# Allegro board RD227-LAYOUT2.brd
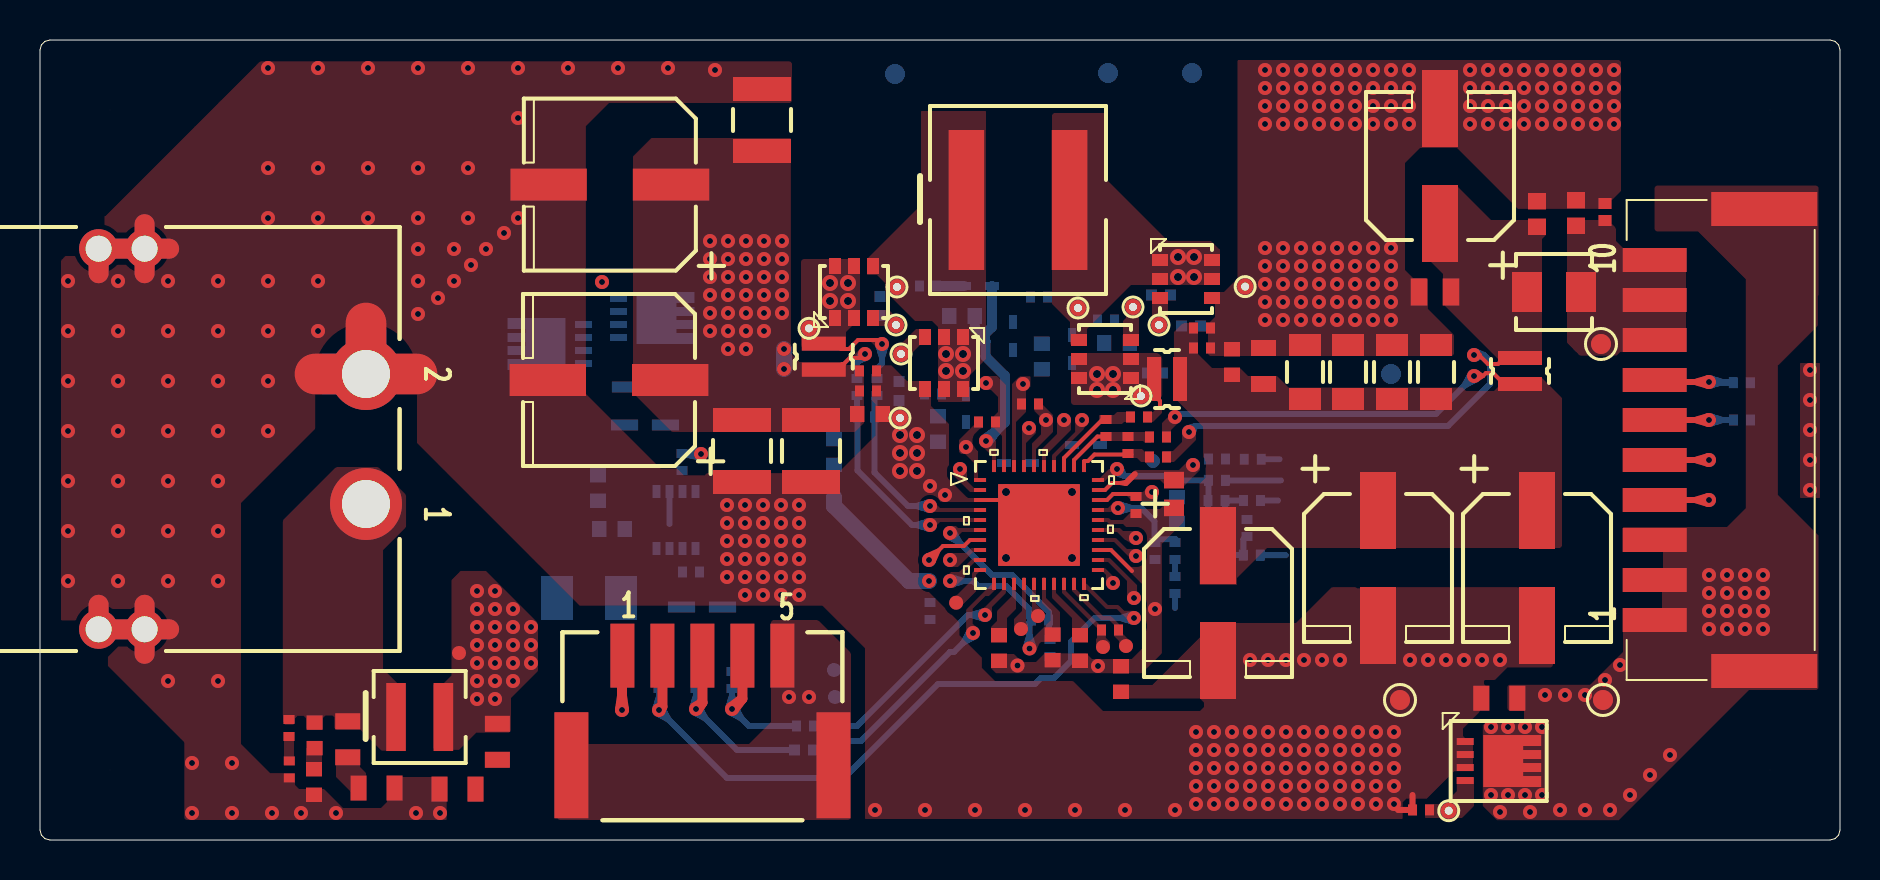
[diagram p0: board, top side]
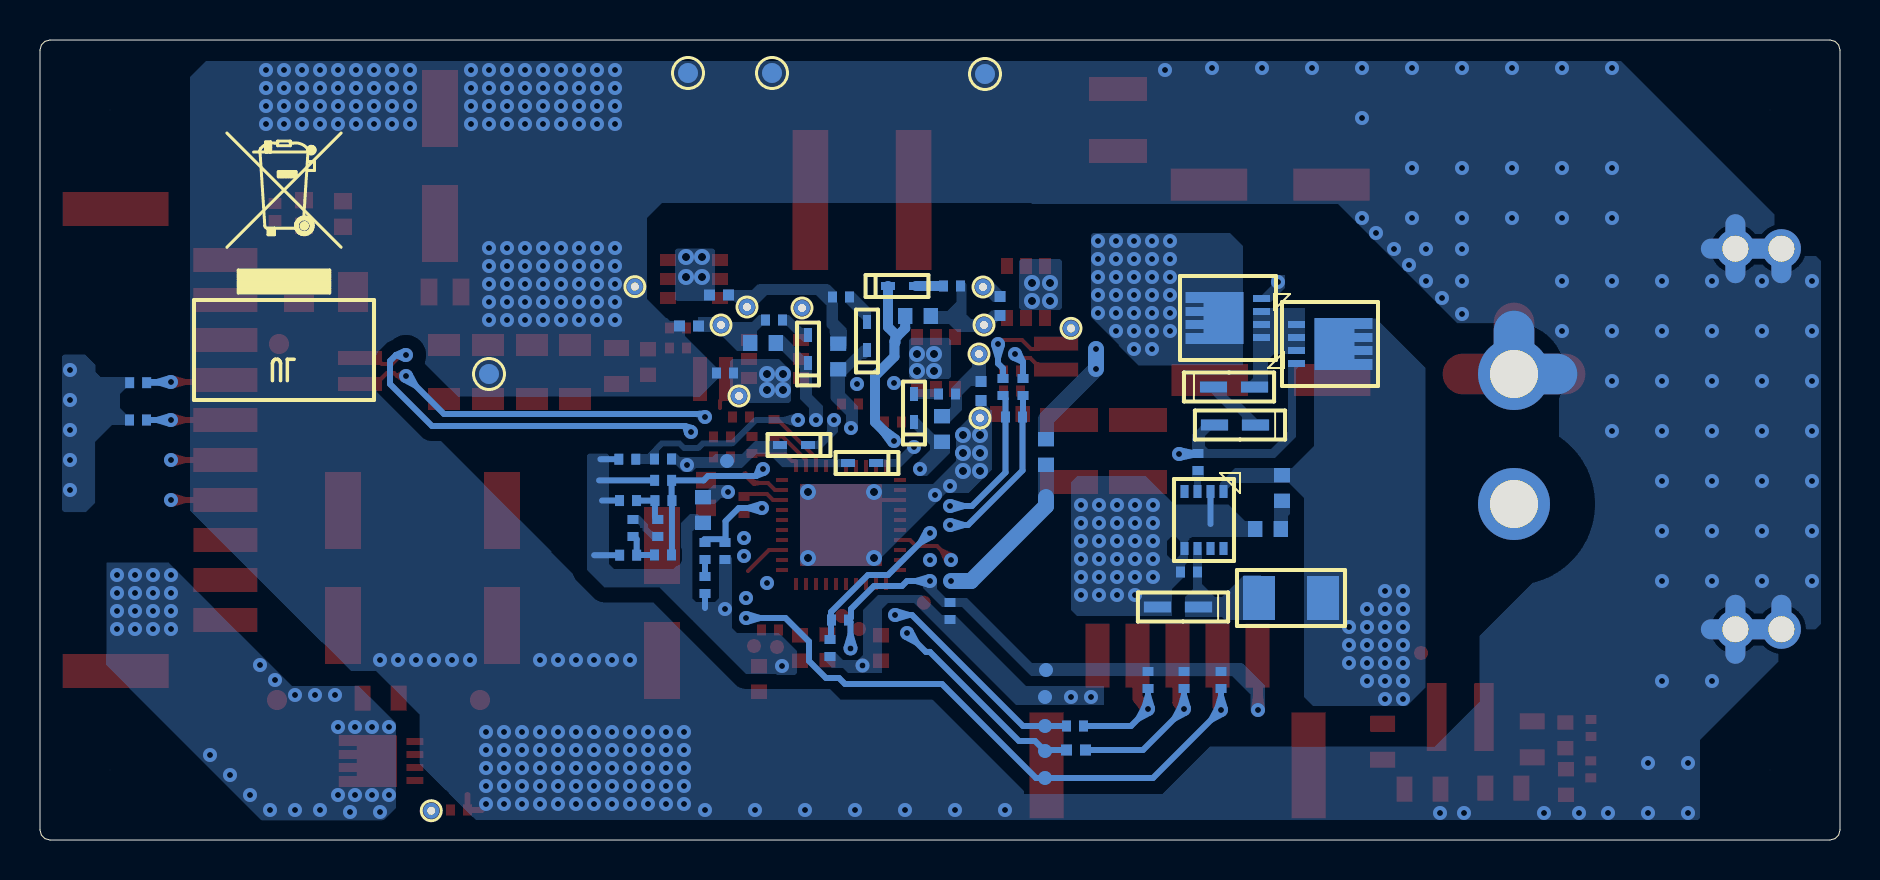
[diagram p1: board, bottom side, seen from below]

Outline 90 x 40 mm; copper layers: TOP, CONDUCTIVE2, CONDUCTIVE3, BOTTOM. Coordinates in mm from the lower left corner of the outline.
Outline path: 0,39.5 0.07,39.75 0.25,39.93 0.5,40 89.5,40 89.75,39.93 89.93,39.75 90,39.5 90,0.5 89.93,0.25 89.75,0.07 89.5,0 0.5,0 0.25,0.07 0.07,0.25 0,0.5 0,39.5

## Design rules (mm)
constraint set DEFAULT: 

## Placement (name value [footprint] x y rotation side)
C201  -  [KC00060AKP]  15.39 5.03 90 top
C202  -  [KC00060AKP]  16.83 2.6 180 top
C203  -  [KCK03340AKP]  36.1 36 270 top
C204  -  [KC00080AKP]  41.5 21.3 180 top
C205  -  [KC01340AKP]  13.73 5.23 90 top
C206  -  [KC01340AKP]  13.7 2.9 90 top
C207  -  [DC837K]  28.49 32.77 0 top
C208  -  [KCK03340AKP]  35.1 19.45 90 top
C209  -  [DC834K]  41.4 22.45 180 top
C210  -  [DC834K]  12.45 5.6 90 top
C211  -  [DC834K]  12.47 3.53 90 top
C212  -  [DC837K]  28.45 23 0 top
C213  -  [KCK03340AKP]  38.55 19.45 90 top
C214  -  [DC834K]  41.4 23.45 180 top
C215  -  [KC00060AKP]  22.87 4.91 90 top
C216  -  [KC00060AKP]  20.87 2.55 0 top
C217  -  [DC834K]  47.35 20.9 0 top
C218  -  [DC834K#2]  32.55 13.4 0 bottom
C219  -  [KC01540AKP01#2]  55.75 23.35 180 bottom
C220  -  [DC834K]  49.5 21.8 180 top
C221  -  [KC00080AKP#2]  27.9 17.6 270 bottom
C222  -  [KC00080AKP#2]  28.6 15.55 0 bottom
C223  -  [DC843R]  58.9 11.85 90 top
C224  -  [KC00140AKP]  69.8 23.4 270 top
C225  -  [KC00060AKP]  61.17 23.7 270 top
C226  -  [DC843R]  74.85 13.6 90 top
C227  -  [KC00140AKP]  67.6 23.4 270 top
C228  -  [KC00080AKP]  59.6 23.9 270 top
C229  -  [DC843R]  66.9 13.6 90 top
C230  -  [KC00140AKP]  65.4 23.4 270 top
C231  -  [DC834K]  58.1 24.6 180 top
C232  -  [KC00140AKP]  63.25 23.4 270 top
C233  -  [KC01540AKP01]  58.1 25.6 180 top
C234  -  [KCK02380AKP01]  74.85 31.3 270 top
C235  -  [DC843R]  70 33.7 270 top
C236  -  [KCK02380AKP01]  76.8 31.35 270 top
C237  -  [KC01540AKP01]  78.25 31.4 270 top
C238  -  [KC00060AKP]  72.97 7.09 0 top
C239  -  [KC00080AKP#2]  56.85 16.5 270 bottom
C240  -  [DC834K]  54.8 16.75 90 top
C241  -  [DC834K#2]  44.5 11.45 270 bottom
C242  -  [KC01670AKP]  50.63 9.63 270 top
C243  -  [KC01560AKP]  56.7 17.3 270 top
C244  -  [DC834K#2]  41.3 21.15 180 bottom
C245  -  [KC00080AKP]  47.95 9.6 270 top
C246  -  [KC00080AKP]  52 9.6 270 top
C247  -  [DC834K]  53.3 20.6 90 top
C248  -  [DC834K]  54.4 19.75 90 top
C249  -  [DC834K#2]  85.1 21 0 bottom
C250  -  [DC834K#2]  85.09 22.86 0 bottom
C251  -  [DC834K#2]  55.75 14.45 270 bottom
C252  -  [DC834K#2]  56.75 12.75 270 bottom
C253  -  [DC834K#2]  58.85 17.98 0 bottom
C254  -  [DC834K#2]  60.6 16.97 0 bottom
C255  -  [DC834K#2]  60.35 15.6 270 bottom
CN201  -  [LOCAL_HVH_280_2P_6_5_1]  16.3 16.8 270 top
CN202  -  [LOCAL_502352_0501]  33.12 5.69 0 top
CN203  -  [LOCAL_502352_1000]  84 20 90 top
D201  -  [D8K022]  33.1 11.65 180 bottom
D202  -  [D8101D1AKP]  48.9 18.85 180 bottom
D203  -  [D8101D1AKP]  46.9 27.7 0 bottom
D204  -  [D8101D1AKP]  46.3 21.6 270 bottom
D205  -  [D8101D1AKP]  48.65 25.2 270 bottom
D206  -  [D8101D1AKP]  51.6 24.55 270 bottom
D207  -  [D8101D1AKP]  52.3 19.75 180 bottom
D208  -  [D8K022]  30.25 20.75 180 bottom
D209  -  [D8K022]  30.3 22.65 0 bottom
FL201  -  [KC00080AKP#2]  39.7 19.4 90 bottom
IC201  -  [SN00281AKP]  31.8 16 0 bottom
IC202  -  [LOCAL_MAX25432BATLGV_1]  49.95 15.75 0 top
L201  -  [LOCAL_XEL_4030_471ME_1]  18.98 6.15 0 top
L202  -  [LOCAL_XAL8080_103MED]  48.9 32 0 top
L203  -  [LOCAL_IHLP1212BZEVR2_1]  75.7 27.4 0 top
NOREF  -  [unnamed]  86.5 3.5 0 top
NOREF#2  -  [unnamed]  3.5 36.5 0 top
NOREF#3  -  [unnamed]  86.5 36.5 0 top
NOREF#4  -  [unnamed]  3.5 3.5 0 top
NOREF#5  -  [#2]  77.8 31.35 180 bottom
NOREF#6  -  [#2]  73.3 22 180 bottom
Q201  -  [SN00612AKP]  25.5 24.8 270 bottom
Q202  -  [SN00612AKP]  30.6 26.1 90 bottom
Q203  -  [LOCAL_TSOP6F]  40.7 27.4 0 top
Q204  -  [LOCAL_TSOP6F]  45.2 23.85 180 top
Q205  -  [LOCAL_TSOP6F]  53.25 24.05 90 top
Q206  -  [LOCAL_TSOP6F]  57.3 28.05 270 top
Q207  -  [SN00612AKP]  72.94 3.95 270 top
R201  -  [KC00080AKP#2]  44.9 20.55 90 bottom
R202  -  [KC00080AKP#2]  46.1 26.2 180 bottom
R203  -  [KC01310AKP#2]  44.4 27.7 180 bottom
R204  -  [LOCAL_KRL2012]  39.19 24.17 90 top
R205  -  [LOCAL_KRL2012]  56.35 23.05 0 top
R206  -  [LOCAL_KRL2012]  74 23.45 90 top
R207  -  [KC01310AKP#2]  44.65 22.3 180 bottom
R208  -  [KC01310AKP#3]  42 26.7 90 bottom
R209  -  [KC01310AKP#3]  42.95 22.45 270 bottom
R210  -  [DR820RF]  27.45 12.1 0 bottom
R211  -  [KC01310AKP#3]  56.05 27.25 0 bottom
R212  -  [KC01310AKP#3]  57.55 25.7 0 bottom
R213  -  [KC01310AKP#2]  49.95 27.15 0 bottom
R214  -  [KC01310AKP#2]  53.3 26 0 bottom
R215  -  [KC00080AKP#2]  50.09 24.18 90 bottom
R216  -  [KC00080AKP#2]  53.85 24.85 0 bottom
R217  -  [DR824K#2]  32.1 18.9 270 bottom
R219  -  [DR810K]  69.75 27.4 0 top
R220  -  [DR824K]  69.05 1.5 0 top
R221  -  [DR824K#2]  34.6 8 90 bottom
R222  -  [DR824K#2]  32.8 8 90 bottom
R223  -  [KC01310AKP#2]  41.85 22.65 270 bottom
R224  -  [KC01310AKP#2]  40.85 22.65 270 bottom
R225  -  [DR824K#2]  30.95 8 90 bottom
R226  -  [DR824K]  53.5 10.5 180 top
R227  -  [KC01310AKP#3]  38.2 4.5 0 bottom
R228  -  [KC01310AKP#2]  38.25 5.7 0 bottom
R229  -  [KC00080AKP]  54.05 8.05 90 top
R230  -  [KC01310AKP]  54.95 21.15 180 top
R231  -  [KC01310AKP]  55.9 20.15 180 top
R232  -  [KC01310AKP]  55.9 19.15 180 top
R233  -  [DR824K#2]  56.75 14.45 270 bottom
R234  -  [KC01310AKP#2]  50 11 180 bottom
R235  -  [DR824K#2]  50.5 9.6 90 bottom
R236  -  [KC00050AKP]  58.83 16.97 0 bottom
R237  -  [KC01310AKP#2]  60.64 19.04 180 bottom
R238  -  [DR824K#2]  59.11 15.6 270 bottom
R239  -  [DR824K#2]  58.85 19.05 180 bottom
R240  -  [DR824K#2]  58.85 14.25 0 bottom
R241  -  [DR824K#2]  60.59 14.24 0 bottom
TP201  -  [TL0_7_A_NOMM]  20.95 9.35 0 top
TP202  -  [TL0_7_A_NOMM]  39.7 17.15 180 bottom
TP203  -  [LOCAL_TL0_4_TH_A]  38.45 25.58 0 top
TP204  -  [LOCAL_TL0_4_TH_A]  42.8 25.75 0 top
TP205  -  [LOCAL_TL0_4_TH_A]  42.85 27.65 0 top
TP206  -  [LOCAL_TL0_4_TH_A]  43.05 24.3 0 top
TP207  -  [LOCAL_TL0_4_TH_A]  43 21.1 0 top
TP208  -  [LOCAL_TL0_4_TH_A]  55.05 22.2 0 top
TP209  -  [LOCAL_TL0_4_TH_A]  54.65 26.65 0 top
TP210  -  [LOCAL_TL0_4_TH_A]  51.9 26.6 0 top
TP211  -  [LOCAL_TL0_4_TH_A]  55.95 25.75 0 top
TP212  -  [LOCAL_TL0_4_TH_A]  60.26 27.67 0 top
TP213  -  [LOCAL_TP_100_A]  78.05 24.8 0 top
TP214  -  [LOCAL_TL0_4_TH_A]  70.44 1.46 0 top
TP215  -  [LOCAL_TP_100_A]  78.15 7 0 top
TP216  -  [LOCAL_TP_100_A]  68 7 0 top
TP217  -  [TL0_7_A_NOMM]  39.7 8.5 180 bottom
TP218  -  [TL0_7_A_NOMM]  39.75 7.15 180 bottom
TP219  -  [TL0_7_A_NOMM]  55.65 18.95 180 bottom
TP220  -  [TL0_7_A_NOMM]  54.3 9.7 0 top
TP221  -  [TL0_7_A_NOMM]  53.15 9.65 0 top
TP222  -  [TL0_7_A_NOMM]  39.75 3.1 180 bottom
TP223  -  [TL0_7_A_NOMM]  39.75 4.45 180 bottom
TP224  -  [TL0_7_A_NOMM]  39.75 5.7 180 bottom
TP225  -  [TL0_7_A_NOMM]  45.81 11.86 0 top
TP226  -  [TL0_7_A_NOMM]  49.05 10.55 0 top
TP227  -  [TL0_7_A_NOMM]  49.9 11.2 0 top
TP231  -  [LOCAL_TP_100_A]  67.55 23.3 180 bottom
TP232  -  [LOCAL_TP_100_A]  57.6 38.35 180 bottom
TP233  -  [LOCAL_TP_100_A]  53.4 38.35 180 bottom
TP234  -  [LOCAL_TP_100_A]  42.75 38.3 180 bottom

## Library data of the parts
C201 C202 C215 C216 = GDM03S00003P: alternate symbols: (T:KC00060AKP;B:KC00060BKP)
C203 C208 C213 = GAS030000261: alternate symbols: (T:KCK03340AKP;B:KCK03340BKP)
C204 C221 C222 C228 C239 C245 C246 = GDM03S000024: alternate symbols: (T:KC00080AKP;B:KC00080BKP)
C205 C206 = GAS030000041: alternate symbols: (T:KC01340AKP;B:KC01340BKP)
C207 C212 = GDM030001780: alternate symbols: (T:DC837K;B:DC937K)
C209 C214 C217 C218 C220 C231 C240 C241 C255 = G924015104Q0: alternate symbols: (T:DC834K;B:DC934K)
C210 C211 = G5103106P106: alternate symbols: (T:DC834K;B:DC934K)
C219 C233 C237 = GAS030000078: alternate symbols: (T:KC01540AKP01,DC834K,KC01540AKP;B:KC01540BKP01,DC834K,KC01540BKP)
C223 C226 C229 C235 = GDM030000304: alternate symbols: (T:DC843R;B:DC943R)
C224 C227 C230 C232 = GDM03S000017: alternate symbols: (T:KC00140AKP;B:KC00140BKP)
C225 C238 = GDM03S000036: alternate symbols: (T:KC00060AKP;B:KC00060BKP)
C234 C236 = GAS030000086: alternate symbols: (T:KCK02380AKP01;B:KCK02380BKP01)
C242 = GDM030002537: alternate symbols: (T:KC01670AKP;B:KC01670BKP)
C243 = GDM030002140: alternate symbols: (T:KC01560AKP;B:KC01560BKP)
C244 C247 C248 C251 = G5103105X103: alternate symbols: (T:DC834K;B:DC934K)
C249 C250 = G5103106G107: alternate symbols: (T:DC834K;B:DC934K)
C252 = G36030133517: alternate symbols: (T:DC834K;B:DC934K)
C253 = G510310FQ104: alternate symbols: (T:DC834K;B:DC934K)
C254 = G510310E1104: alternate symbols: (T:DC834K;B:DC934K)
CN201 = HVH-280-2P-6_5DS: alternate symbols: (T:Local_HVH_280_2P_6_5_1;B:Local_HVH_280_2P_6_5_1_B)
CN202 = 502352-0501: alternate symbols: (T:Local_502352_0501;B:Local_502352_0501_B)
CN203 = 502352-1000: alternate symbols: (T:Local_502352_1000;B:Local_502352_1000_B)
D201 D208 D209 = K4200015: alternate symbols: (T:D8K022;B:D9K022)
D202-D207 = GDM42S000008: alternate symbols: (T:D8101D1AKP;B:D8101D1BKP)
FL201 = GDM130000101: alternate symbols: (T:KC00080AKP;B:KC00080BKP)
IC201 = GDM410000462: alternate symbols: (T:SN00281AKP;B:SN00281BKP)
IC202 = MAX25432BATLGV+
L201 = XEL-4030-471MEC: alternate symbols: (T:Local_XEL_4030_471ME_1;B:Local_XEL_4030_471ME_1_B)
L202 = XAL8080-103MED: alternate symbols: (T:Local_XAL8080_103MED;B:Local_XAL8080_103MED_B)
L203 = IHLP1212BZEVR22M5A: alternate symbols: (T:Local_IHLP1212BZEVR2_1;B:Local_IHLP1212BZEVR2_1_B)
Q201 Q202 Q207 = K4100929: alternate symbols: (T:SN00612AKP;B:SN00612BKP)
Q203-Q206 = GDM410000109
R201 R202 R215 R216 R229 = G8800256207A: alternate symbols: (T:KC00080AKP;B:KC00080BKP)
R203 R207-R209 R211-R214 R223 R224 R227 R228 R230-R232 R234 R237 = GAS010000128: alternate symbols: (T:KC01310AKP,DC934K,DR924K,DR824K;B:KC01310BKP,DC934K,DR924K,DR824K)
R204 R205 = KRL2012E-M-R003-F
R206 = KRL2012E-M-R005-F: alternate symbols: (T:Local_KRL2012;B:Local_KRL2012_B)
R210 = G510110RM109: alternate symbols: (T:DR820RF;B:DR901RF)
R217 = G510110CB102: alternate symbols: (T:DR824K;B:DR924K)
R219 = G510110AC101: alternate symbols: (T:DR810K;B:DR910K)
R220 R225 = G510110EF108: alternate symbols: (T:DR824K;B:DR924K)
R221 R222 = G510110E7102: alternate symbols: (T:DR824K;B:DR924K)
R226 R233 R235 R238-R241 = G510110M9109: alternate symbols: (T:DR824K;B:DR924K)
R236 = GDM010002829: alternate symbols: (T:KC00050AKP;B:KC00050BKP)
TP201 TP202 TP217-TP227 = TL0.7_noMM: alternate symbols: (T:TL0_7_A_noMM;B:TL0_7_B_noMM)
TP203-TP212 TP214 = TL0.4_TH: alternate symbols: (T:Local_TL0_4_TH_A;B:Local_TL0_4_TH_B)
TP213 TP215 TP216 TP231-TP234 = TP-100: alternate symbols: (T:Local_TP_100_A;B:Local_TP_100_B)

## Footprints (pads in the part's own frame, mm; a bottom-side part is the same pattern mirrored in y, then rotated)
D8K022
  rect 1.36x0.55 smd: A(-1.025,0) C(1.025,0)
D8101D1AKP
  rect 0.7x0.4 smd: A(-0.7,0) C(0.7,0)
DC834K
  rect 0.45x0.55 smd: 1(-0.425,0) 2(0.425,0)
DC834K#2
  rect 0.45x0.55 smd: 1(0.425,0) 2(-0.425,0)
DC837K
  rect 3.82x1.6 smd: 1(-3.06,0) 2(3.06,0)
DC843R
  rect 3.85x1.8 smd: 1(-2.875,0) 2(2.875,0)
DR810K
  rect 0.83x1.35 smd: 1(-0.8,0) 2(0.8,0)
DR820RF
  rect 1.6x2.2 smd: 1(1.6,0) 2(-1.6,0)
DR824K
  rect 0.45x0.55 smd: 1(-0.425,0) 2(0.425,0)
DR824K#2
  rect 0.45x0.55 smd: 1(0.425,0) 2(-0.425,0)
KC00050AKP
  rect 0.45x0.55 smd: 1(0.425,0) 2(-0.425,0)
KC00060AKP
  rect 0.8x1.25 smd: 1(-0.9,0) 2(0.9,0)
KC00080AKP
  rect 0.72x0.8 smd: 1(-0.64,0) 2(0.64,0)
KC00080AKP#2
  rect 0.72x0.8 smd: 1(0.64,0) 2(-0.64,0)
KC00140AKP
  rect 1.1x1.6 smd: 1(-1.35,0) 2(1.35,0)
KC01310AKP
  rect 0.45x0.55 smd: 1(-0.425,0) 2(0.425,0)
KC01310AKP#2
  rect 0.45x0.55 smd: 1(0.425,0) 2(-0.425,0)
KC01310AKP#3
  rect 0.55x0.55 smd: 1(0.475,0) 2(-0.475,0)
KC01340AKP
  rect 0.72x0.8 smd: 1(-0.64,0) 2(0.64,0)
KC01540AKP01
  rect 0.45x0.55 smd: 1(-0.425,0) 2(0.425,0)
KC01540AKP01#2
  rect 0.45x0.55 smd: 1(0.425,0) 2(-0.425,0)
KC01560AKP
  rect 0.83x1 smd: 1(-0.695,0) 2(0.695,0)
KC01670AKP
  rect 0.72x0.8 smd: 1(-0.64,0) 2(0.64,0)
KCK02380AKP01
  rect 0.82x0.9 smd: 1(-0.64,0) 2(0.64,0)
KCK03340AKP
  rect 1.2x2.9 smd: 1(-1.55,0) 2(1.55,0)
LOCAL_502352_0501
  rect 1.2x3.2 smd: 1(-4,3.53) 2(-2,3.53) 3(0,3.53) 4(2,3.53) 5(4,3.53)
  rect 1.7x5.3 smd: 1T(-6.55,-1.95) 2T(6.55,-1.95)
LOCAL_502352_1000
  rect 1.2x3.2 smd: 1(-9,3.265) 2(-7,3.265) 3(-5,3.265) 4(-3,3.265) 5(-1,3.265) 6(1,3.265) 7(3,3.265) 8(5,3.265) 9(7,3.265) 10(9,3.265)
  rect 1.7x5.3 smd: 1T(-11.55,-2.215) 2T(11.55,-2.215)
LOCAL_HVH_280_2P_6_5_1
  round 3.6 hole 2.4: 1(0,0) 2(-6.5,0)
  round 1.95 hole 1.3: 1T(6.265,-13.37) 2T(6.265,-11.07) 3T(-12.765,-11.07) 4T(-12.765,-13.37)
LOCAL_IHLP1212BZEVR2_1
  custom 0.375x0.375 smd: 1(-1.35,0) 2(1.35,0)
LOCAL_KRL2012
  custom 0.175x0.175 smd: 1(-0.65,0) 2(0.65,0)
LOCAL_MAX25432BATLGV_1
  custom 0.05x0.05 smd: 1(-2.948,2.25) 2(-2.948,1.75) 3(-2.948,1.25) 4(-2.948,0.75) 5(-2.948,0.25) 6(-2.948,-0.25) 7(-2.948,-0.75) 8(-2.948,-1.25) 9(-2.948,-1.75) 10(-2.948,-2.25) 11(-2.25,-2.948) 12(-1.75,-2.948) 13(-1.25,-2.948) 14(-0.75,-2.948) 15(-0.25,-2.948) 16(0.25,-2.948) 17(0.75,-2.948) 18(1.25,-2.948) 19(1.75,-2.948) 20(2.25,-2.948) 21(2.948,-2.25) 22(2.948,-1.75) 23(2.948,-1.25) 24(2.948,-0.75) 25(2.948,-0.25) 26(2.948,0.25) 27(2.948,0.75) 28(2.948,1.25) 29(2.948,1.75) 30(2.948,2.25) 31(2.25,2.948) 32(1.75,2.948) 33(1.25,2.948) 34(0.75,2.948) 35(0.25,2.948) 36(-0.25,2.948) 37(-0.75,2.948) 38(-1.25,2.948) 39(-1.75,2.948) 40(-2.25,2.948)
  custom 1.022x1.022 smd: 41(0,0)
LOCAL_TL0_4_TH_A
  round 0.8 hole 0.4: 1(0,0)
LOCAL_TP_100_A
  custom 0.25x0.25 smd: 1(0,0)
LOCAL_TSOP6F
  rect 0.6x0.8 smd: 1(-0.95,-1.3) 2(0,-1.3) 3(0.95,-1.3) 4(0.95,1.3) 5(0,1.3) 6(-0.95,1.3)
LOCAL_XAL8080_103MED
  custom 0.445x0.445 smd: 1(-2.58,0) 2(2.58,0)
LOCAL_XEL_4030_471ME_1
  custom 0.245x0.245 smd: 1(-1.185,0) 2(1.185,0)
SN00281AKP
  rect 0.4x0.65 smd: 1(-0.975,-1.425) 2(-0.325,-1.425) 3(0.325,-1.425) 4(0.975,-1.425) 5(0.975,1.425) 6(0.325,1.425) 7(-0.325,1.425) 8(-0.975,1.425)
SN00612AKP
  rect 0.35x0.85 smd: 1(-0.975,-1.675) 2(-0.325,-1.675) 3(0.325,-1.675) 4(0.975,-1.675)
  custom 0.65x0.65 smd: 5(0,0.675)
TL0_7_A_NOMM
  round 0.7 smd: 1(0,0)
unnamed
  round 0.01 hole 3 unplated: (0,0)

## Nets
GND_A: C239.1 C240.1 C241.1 C242.2 C243.2 C245.2 C246.2 C249.1 C250.1 C251.1 C252.1 C253.1 C254.1 CN202.1T CN202.2T CN202.5 IC202.23 IC202.26 R229.2 R235.2 R237.2 R241.1 TP218.1
GND_P: C202.1 C203.1 C204.1 C206.1 C207.1 C208.1 C209.1 C211.1 C212.1 C213.1 C214.1 C216.1 C218.1 C219.2 C222.1 C223.1 C224.1 C225.1 C226.1 C227.1 C228.1 C229.1 C230.1 C231.1 C232.1 C233.1 C234.1 C235.1 C236.1 C237.1 C238.1 CN201.1T CN201.2 CN201.2T CN201.3T CN201.4T D201.A IC201.2 IC201.5 IC202.3 IC202.41 Q204.4 Q206.4 Q207.1 Q207.2 Q207.3 R209.1 R212.1 R219.1 R220.1 R229.1 TP207.1 TP212.1 TP216.1 TP231.1 TP232.1 TP233.1 TP234.1
VBAT: C239.2 C240.2 FL201.2 IC202.28 TP202.1
VBUS: C236.2 C237.2 CN203.8 CN203.9 CN203.10 L203.2 TP213.1
VDD: C241.2 C242.1 CN202.1 IC202.9 IC202.16 R221.1 R222.1 R225.1 R234.1 TP217.1
VIN: C201.2 C205.2 C210.2 CN201.1 L201.1
VIN2: C215.2 C221.2 IC201.1 L201.2 Q201.5 R210.2 TP201.1
ADDR: IC202.34 R237.1 R239.2
ALERT: CN202.2 IC202.20 R225.2 TP222.1
BIAS: C243.1 D202.A D207.A IC202.29 R239.1 TP219.1
BST1: C217.1 D202.C IC202.1
BST2: C220.1 D207.C IC202.36
CSN1: Q203.1 Q203.2 Q203.5 Q203.6 R204.2 R223.2 TP203.1
CSN2: C234.2 C235.2 L203.1 R206.2 R219.2 R232.1
CSP1: C203.2 C204.2 C207.2 C208.2 C209.2 C212.2 C213.2 C214.2 FL201.1 Q202.5 R204.1 R224.2
CSP2: C219.1 Q205.1 Q205.2 Q205.5 Q205.6 R205.1 R230.1 TP208.1
DH1: D203.C IC202.40 R202.2
DH1_Q: Q203.3 R202.1 R203.1 R208.2 TP204.1
DH2: D205.C IC202.37 R215.2
DH2_Q: Q205.3 R211.2 R213.1 R215.1 TP209.1
DL1: D204.C IC202.2 R201.2
DL1_Q: Q204.3 R201.1 R207.1 R209.2 TP206.1
DL2: D206.C IC202.35 R216.2
DL2_Q: Q206.3 R212.2 R214.1 R216.1 TP211.1
GDRV: IC202.8 Q207.4 R220.2 TP214.1
HVCC1: C250.2 CN203.7 IC202.25
HVCC2: C249.2 CN203.6 IC202.24
HVDM: CN203.5 IC202.21
HVDP: CN203.4 IC202.22
HVEN: IC202.6 R234.2 R235.1
LX1: C217.2 IC202.39 L202.1 Q203.4 Q204.1 Q204.2 Q204.5 Q204.6 R208.1 TP205.1
LX2: C220.2 IC202.38 L202.2 Q205.4 Q206.1 Q206.2 Q206.5 Q206.6 R211.1 TP210.1
OUT: C223.2 C224.2 C225.2 C226.2 C227.2 C228.2 C229.2 C230.2 C231.2 C232.2 C233.2 R205.2 R206.1 R231.1
SCL: CN202.3 R222.2 R227.2
SDA: CN202.4 R221.2 R228.2
SHLD_SNS: C238.2 CN203.1 CN203.1T CN203.2 CN203.2T CN203.3 IC202.7 Q207.5 TP215.1
SIG247: C218.2 D201.C IC201.6 R210.1
SIG310: C251.2 IC202.27 R233.2
SIG311: C252.2 R233.1
SIG313: C254.2 R236.1 R238.2
SIG316: C255.1 R240.1 R241.2
SIG317: C255.2 R238.1
SIG318: C253.2 IC202.30 R236.2 R240.2
SIG319: C247.1 C248.2 IC202.32 R231.2
SIG324: C248.1 IC202.31 R232.2
SIG328: C247.2 IC202.33 R230.2
SIG335: C244.1 IC202.5 R224.1
SIG337: C244.2 IC202.4 R223.1
SIG341: IC202.10 TP225.1
SIG344: IC202.19 R226.1 TP220.1
SIG345: IC202.18 R226.2 TP221.1
SIG346: C245.1 IC202.13
SIG347: C246.1 IC202.17
SIG349: IC202.14 TP226.1
SIG350: IC202.15 TP227.1
SIG369: IC202.11 R227.1 TP223.1
SIG370: IC202.12 R228.1 TP224.1
SIG395: C201.1 C202.2
SIG396: C205.1 C206.2
SIG397: C210.1 C211.2
SIG411: C215.1 C216.2
SIG422: D203.A R203.2
SIG423: D204.A R207.2
SIG424: C221.1 C222.2
SIG425: D205.A R213.2
SIG426: D206.A R214.2
SIG433: IC201.3 R217.1
SIG436: D209.A Q201.1 Q201.2 Q201.3 Q202.1 Q202.2 Q202.3
SIG437: D208.C D209.C
SIG438: D208.A Q201.4 Q202.4 R217.2

Pads without a net: IC201 4 7 8

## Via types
v1: diameter 0.7, hole 0.3, TOP to BOTTOM, 444 vias
v2: diameter 0.8, hole 0.4, TOP to BOTTOM, 26 vias

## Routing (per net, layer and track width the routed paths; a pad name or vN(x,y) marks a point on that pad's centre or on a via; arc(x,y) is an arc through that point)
GND_A: length 8.7
  TOP w0.2: 54.6,13.45 53.55,14.5 IC202.23
  BOTTOM w0.3: C253.1 62.05,17.98 ; R241.1 62.29,14.24 ; 61.11,19.04 61.98,19.04 ; C254.1 61.9,16.97 ; C252.1 56.75,11.6
  vias: v1(37.45,7.15) v1(38.45,7.15) v1(48.88,8.72) v1(52.9,8.7) v1(55.75,11.55) v1(88.5,23.5) v1(88.5,22) v1(88.5,20.5) v1(88.5,19) v1(88.5,17.5)
GND_P: length 95.4
  TOP w0.2: IC202.3 48.3,17
  TOP w0.3: 68.63,2.25 R220.1 67.9,1.5
  TOP w1: CN201.2T 6.46,10.54 ; CN201.2T 5.23,11.76 ; CN201.2T CN201.1T 2.93,11.76 ; CN201.2T 5.23,9.31 ; CN201.3T 5.23,28.34 ; CN201.3T 6.46,29.57 ; CN201.3T 5.23,30.79 ; CN201.3T CN201.4T 2.93,28.34
  TOP w2.032: CN201.2 18.85,23.3 ; CN201.2 16.3,25.85 ; CN201.2 13.75,23.3
  CONDUCTIVE2 w1: CN201.3T 5.23,28.09 ; CN201.3T 5.23,31.04 ; CN201.3T CN201.4T 2.93,28.06 ; CN201.3T 6.71,29.57 ; CN201.2T 6.71,10.54 ; CN201.2T CN201.1T 2.93,12.01 ; CN201.2T 5.23,12.01 ; CN201.2T 5.23,9.06
  CONDUCTIVE2 w2.032: CN201.2 16.3,25.6 ; CN201.2 14,23.3 ; CN201.2 16.3,21.6 ; CN201.2 18.6,23.3
  CONDUCTIVE3 w1: CN201.2T 6.71,10.54 ; CN201.2T CN201.1T 2.93,12.01 ; CN201.2T 5.23,9.06 ; CN201.2T 5.23,12.01 ; CN201.3T 6.71,29.57 ; CN201.3T CN201.4T 2.93,27.97 ; CN201.3T 5.23,27.97 ; CN201.3T 5.23,31.04
  CONDUCTIVE3 w2.032: 16.3,25.6 CN201.2 ; CN201.2 14,23.3 ; CN201.2 16.3,21.65 ; CN201.2 18.6,23.3
  BOTTOM w0.3: IC201.2 31.48,15.8
  BOTTOM w1: CN201.2T 5.23,11.76 ; CN201.2T 5.23,9.31 ; CN201.2T CN201.1T 2.93,11.76 ; CN201.2T 6.46,10.54 ; 2.93,28.34 CN201.4T CN201.3T ; CN201.3T 5.23,30.79 ; CN201.3T 5.23,28.34 ; CN201.3T 6.46,29.57
  BOTTOM w2.032: 16.3,25.45 CN201.2 14.15,23.3
  vias: v1(1.4,27.95) v1(1.4,25.45) v1(1.4,22.95) v1(1.4,20.45) v1(1.4,17.95) v1(1.4,15.45) v1(1.4,12.95) v1(3.9,27.95) v1(3.9,25.45) v1(3.9,22.95) v1(3.9,20.45) v1(3.9,17.95) v1(3.9,15.45) v1(3.9,12.95) v1(6.4,27.95) v1(6.4,25.45) v1(6.4,22.95) v1(6.4,20.45) v1(6.4,17.95) v1(6.4,15.45) v1(6.4,12.95) v1(6.4,7.95) v1(7.6,3.85) v1(7.6,1.35) v1(8.9,27.95) v1(8.9,25.45) v1(8.9,22.95) v1(8.9,20.45) v1(8.9,17.95) v1(8.9,15.45) v1(8.9,12.95) v1(8.9,7.95) v1(9.6,3.85) v1(9.6,1.35) v1(11.4,38.6) v1(11.4,33.6) v1(11.4,31.1) v1(11.4,27.95) v1(11.4,25.45) v1(11.4,22.95) v1(11.4,20.45) v1(11.6,1.35) v1(13.05,1.35) v1(13.9,38.6) v1(13.9,33.6) v1(13.9,31.1) v1(13.9,27.95) v1(13.9,25.45) v1(14.8,1.35) v1(16.4,38.6) v1(16.4,33.6) v1(16.4,31.1) v1(18.8,1.35) v1(18.9,38.6) v1(18.9,33.6) v1(18.9,31.1) v1(18.9,29.55) v1(18.9,27.95) v1(18.9,26.3) v1(19.9,27.1) v1(20,1.35) v1(20.7,29.55) v1(20.7,27.95) v1(21.4,38.6) v1(21.4,33.6) v1(21.4,31.1) v1(21.55,28.75) v1(22.3,29.55) v1(23.2,30.35) v1(23.9,38.6) v1(23.9,36.1) v1(23.9,31.1) v1(26.4,38.6) v1(28.9,38.6) v1(31.4,38.6) v1(33.75,38.5) v1(34.35,16.75) v1(34.35,15.85) v1(34.35,14.95) v1(34.35,14.05) v1(34.35,13.15) v1(35.25,16.75) v1(35.25,15.85) v1(35.25,14.95) v1(35.25,14.05) v1(35.25,13.15) v1(35.25,12.25) v1(36.15,16.75) v1(36.15,15.85) v1(36.15,14.95) v1(36.15,14.05) v1(36.15,13.15) v1(36.15,12.25) v1(37.05,16.75) v1(37.05,15.85) v1(37.05,14.95) v1(37.05,14.05) v1(37.05,13.15) v1(37.05,12.25) v1(37.95,16.75) v1(37.95,15.85) v1(37.95,14.95) v1(37.95,14.05) v1(37.95,13.15) v1(37.95,12.25) v1(41.75,1.5) v1(44.25,1.5) v1(44.5,17.7) v1(45.25,17.25) v1(46.75,1.5) v1(49.25,1.5) v1(51.75,1.5) v1(54.25,1.5) v1(56.75,1.5) v1(57.8,5.4) v1(57.8,4.5) v1(57.8,3.6) v1(57.8,2.7) v1(57.8,1.8) v1(58.7,5.4) v1(58.7,4.5) v1(58.7,3.6) v1(58.7,2.7) v1(58.7,1.8) v1(59.6,5.4) v1(59.6,4.5) v1(59.6,3.6) v1(59.6,2.7) v1(59.6,1.8) v1(60.5,9) v1(60.5,5.4) v1(60.5,4.5) v1(60.5,3.6) v1(60.5,2.7) v1(60.5,1.8) v1(61.25,38.5) v1(61.25,37.6) v1(61.25,36.7) v1(61.25,35.8) v1(61.25,29.6) v1(61.25,28.7) v1(61.25,27.8) v1(61.25,26.9) v1(61.25,26) v1(61.4,9) v1(61.4,5.4) v1(61.4,4.5) v1(61.4,3.6) v1(61.4,2.7) v1(61.4,1.8) v1(62.15,38.5) v1(62.15,37.6) v1(62.15,36.7) v1(62.15,35.8) v1(62.15,29.6) v1(62.15,28.7) v1(62.15,27.8) v1(62.15,26.9) v1(62.15,26) v1(62.3,9) v1(62.3,5.4) v1(62.3,4.5) v1(62.3,3.6) v1(62.3,2.7) v1(62.3,1.8) v1(63.05,38.5) v1(63.05,37.6) v1(63.05,36.7) v1(63.05,35.8) v1(63.05,29.6) v1(63.05,28.7) v1(63.05,27.8) v1(63.05,26.9) v1(63.05,26) v1(63.2,9) v1(63.2,5.4) v1(63.2,4.5) v1(63.2,3.6) v1(63.2,2.7) v1(63.2,1.8) v1(63.95,38.5) v1(63.95,37.6) v1(63.95,36.7) v1(63.95,35.8) v1(63.95,29.6) v1(63.95,28.7) v1(63.95,27.8) v1(63.95,26.9) v1(63.95,26) v1(64.1,9) v1(64.1,5.4) v1(64.1,4.5) v1(64.1,3.6) v1(64.1,2.7) v1(64.1,1.8) v1(64.85,38.5) v1(64.85,37.6) v1(64.85,36.7) v1(64.85,35.8) v1(64.85,29.6) v1(64.85,28.7) v1(64.85,27.8) v1(64.85,26.9) v1(64.85,26) v1(65,9) v1(65,5.4) v1(65,4.5) v1(65,3.6) v1(65,2.7) v1(65,1.8) v1(65.75,38.5) v1(65.75,37.6) v1(65.75,36.7) v1(65.75,35.8) v1(65.75,29.6) v1(65.75,28.7) v1(65.75,27.8) v1(65.75,26.9) v1(65.75,26) v1(65.9,5.4) v1(65.9,4.5) v1(65.9,3.6) v1(65.9,2.7) v1(65.9,1.8) v1(66.65,38.5) v1(66.65,37.6) v1(66.65,36.7) v1(66.65,35.8) v1(66.65,29.6) v1(66.65,28.7) v1(66.65,27.8) v1(66.65,26.9) v1(66.65,26) v1(66.8,5.4) v1(66.8,4.5) v1(66.8,3.6) v1(66.8,2.7) v1(66.8,1.8) v1(67.55,38.5) v1(67.55,37.6) v1(67.55,36.7) v1(67.55,35.8) v1(67.55,29.6) v1(67.55,28.7) v1(67.55,27.8) v1(67.55,26.9) v1(67.55,26) v1(67.7,5.4) v1(67.7,4.5) v1(67.7,3.6) v1(67.7,2.7) v1(67.7,1.8) v1(68.45,38.5) v1(68.45,37.6) v1(68.45,36.7) v1(68.45,35.8) v1(68.5,9) v1(69.4,9) v1(70.3,9) v1(71.2,9) v1(71.5,38.5) v1(71.5,37.6) v1(71.5,36.7) v1(71.5,35.8) v1(72.1,9) v1(72.4,38.5) v1(72.4,37.6) v1(72.4,36.7) v1(72.4,35.8) v1(73,9) v1(73.3,38.5) v1(73.3,37.6) v1(73.3,36.7) v1(73.3,35.8) v1(74.2,38.5) v1(74.2,37.6) v1(74.2,36.7) v1(74.2,35.8) v1(75.1,38.5) v1(75.1,37.6) v1(75.1,36.7) v1(75.1,35.8) v1(76,38.5) v1(76,37.6) v1(76,36.7) v1(76,35.8) v1(76.9,38.5) v1(76.9,37.6) v1(76.9,36.7) v1(76.9,35.8) v1(77.8,38.5) v1(77.8,37.6) v1(77.8,36.7) v1(77.8,35.8) v1(78.7,38.5) v1(78.7,37.6) v1(78.7,36.7) v1(78.7,35.8) v2(43,20.25) v2(43,19.35) v2(43,18.45) v2(43.85,20.25) v2(43.85,19.35) v2(43.85,18.45) v2(48.3,17.4) v2(48.3,14.1) v2(51.6,17.4) v2(51.6,14.1)
VBAT: length 9
  TOP w0.2: IC202.28 53.35,17 53.65,17.3 54.92,17.3
  BOTTOM w0.3: 55.65,17.45 v1(55.6,17.4)
  BOTTOM w0.8: v1(44.45,12.95) 43.45,12.95 39.7,16.7 TP202.1
VDD: length 9.3
  TOP w0.5: v1(29.1,6.5) 29.1,9.2
  BOTTOM w0.3: v1(49.48,9.57) 49.48,10.9 R234.1 49.45,11.12 49.45,11.55 48.3,12.7 46.9,12.7 46.65,12.95 v1(45.5,12.95)
VIN2:
  vias: v1(21.85,12.45) v1(21.85,11.55) v1(21.85,10.65) v1(21.85,9.75) v1(21.85,8.85) v1(21.85,7.95) v1(21.85,7.05) v1(22.75,12.45) v1(22.75,11.55) v1(22.75,10.65) v1(22.75,9.75) v1(22.75,8.85) v1(22.75,7.95) v1(22.75,7.05) v1(23.65,11.55) v1(23.65,10.65) v1(23.65,9.75) v1(23.65,8.85) v1(23.65,7.95) v1(24.55,10.65) v1(24.55,9.75) v1(24.55,8.85)
ADDR:
  vias: v1(52.1,21)
ALERT: length 32.9
  TOP w0.5: v1(30.95,6.5) 31.12,6.67 CN202.2
  BOTTOM w0.3: R225.2 v1(30.95,6.5) 34.35,3.1 TP222.1 40.2,3.1 44.9,7.8 49.75,7.8 50.05,8.1 50.7,8.1 51.55,8.95 51.55,9.92 52.73,11.1 v1(54.7,11.1)
BIAS: length 2.2
  TOP w0.2: 54.3,17.85 53.6,17.85 53.25,17.5 IC202.29
  TOP w0.3: 54.3,17.85 54.74,18.29
  vias: v1(57.65,18.75)
BST1:
  vias: v1(46.3,19.65)
BST2:
  vias: v1(50.3,21)
CSN1: length 4.1
  TOP w0.2: 40.05,24.55 40.45,24.55 40.9,25 41.9,25 v1(42.1,24.8)
  BOTTOM w0.3: v1(42.1,24.8) 42.1,23.83 41.85,23.58 R223.2
  vias: v2(39.5,27.85) v2(39.5,26.95) v2(40.4,27.85) v2(40.4,26.95)
CSN2: length 19.7
  TOP w0.2: v1(71.7,24.25) 72,24.25 72,24.2 72.4,23.8 72.9,23.8 73,23.9
  BOTTOM w0.3: v1(57.45,20.4) 57.75,20.7 70.4,20.7 72.5,22.8 72.5,23.95 72.2,24.25 v1(71.7,24.25)
CSP1: length 3.7
  TOP w0.2: v1(41.25,24.3) 41.05,24.1 40.49,24.1 40.19,23.8 40.1,23.8
  BOTTOM w0.3: v1(41.25,24.3) 40.85,23.9 R224.2
  BOTTOM w0.8: v1(37.2,24.55) v1(37.2,23.55)
  vias: v1(33.5,29.95) v1(33.5,29.05) v1(33.5,28.15) v1(33.5,27.25) v1(33.5,26.35) v1(33.5,25.45) v1(34.4,29.95) v1(34.4,29.05) v1(34.4,28.15) v1(34.4,27.25) v1(34.4,26.35) v1(34.4,25.45) v1(34.4,24.55) v1(35.3,29.95) v1(35.3,29.05) v1(35.3,28.15) v1(35.3,27.25) v1(35.3,26.35) v1(35.3,25.45) v1(35.3,24.55) v1(36.2,29.95) v1(36.2,29.05) v1(36.2,28.15) v1(36.2,27.25) v1(36.2,26.35) v1(36.2,25.45) v1(37.1,29.95) v1(37.1,29.05) v1(37.1,28.15) v1(37.1,27.25) v1(37.1,26.35)
CSP2: length 1.2
  TOP w0.2: 56,21.6 56,21.95 55.55,22.4 55.55,22.2
  vias: v2(52.85,23.3) v2(52.85,22.5) v2(53.65,23.3) v2(53.65,22.5)
DH1: length 10.1
  BOTTOM w0.5: 47.14,25.19 46.74,25.59 R202.2 ; 47.14,25.19 47.23,25.1 47.23,24.88 47.28,24.93 47.28,24.17 48.25,23.2 48.25,20.9 v1(47.3,19.95) ; 47.14,25.19 47.6,25.65 D203.C
DH2:
  vias: v1(49.45,20.6)
DL1:
  vias: v1(46,18.55)
DL2:
  vias: v1(51.2,21)
GDRV: length 36.8
  CONDUCTIVE3 w0.3: v1(45.5,14) 46.35,13.15 46.35,11.65 46,11.3 46,9.2 48.25,6.95 69.65,6.95 71.75,4.85 71.75,2.78 TP214.1
HVCC1: length 37.1
  TOP w0.3: CN203.7 80.83,22.9 v1(83.45,22.9)
  CONDUCTIVE3 w0.3: v1(83.45,22.9) 75.65,15.1 v1(54.8,15.1)
  BOTTOM w0.3: v1(83.45,22.9) 84.63,22.9 C250.2 83.45,22.86
HVCC2: length 35.3
  TOP w0.3: v1(83.45,21) CN203.6
  CONDUCTIVE3 w0.3: v1(54.8,14.2) 55.94,14.2 56.29,14.55 75.86,14.55 82.31,21 v1(83.45,21)
  BOTTOM w0.3: 84.59,21.02 84.57,21 v1(83.45,21)
HVDM: length 35.1
  TOP w0.3: v1(83.45,19) CN203.5
  CONDUCTIVE3 w0.3: v1(83.45,19) 77.37,12.92 54.52,12.92 54.45,12.85 v1(53.65,12.85)
HVDP: length 33.5
  TOP w0.3: CN203.4 v1(83.45,17)
  CONDUCTIVE3 w0.3: v1(83.45,17) 82.16,17 77.48,12.32 54.92,12.32 v1(54.7,12.1)
HVEN: length 9.1
  BOTTOM w0.2: R235.1 50.42,10.1 R234.2
  BOTTOM w0.3: v1(45.5,15.35) 47.6,13.25 48.6,13.25 50.45,11.4 50.45,9.97 R235.1
LX1: length 8
  CONDUCTIVE2 w0.5: v1(47.3,22.85) 47.3,25.45 45.1,27.65 TP205.1
  vias: v2(45.3,24.3) v2(45.3,23.45) v2(46.15,24.3) v2(46.15,23.45)
LX2: length 5.9
  CONDUCTIVE2 w0.5: TP210.1 50.3,26.6 49.15,25.45 v1(49.15,22.8)
  vias: v2(56.9,29.15) v2(56.9,28.15) v2(57.7,29.15) v2(57.7,28.15)
OUT: length 18.4
  TOP w0.2: v1(71.7,23.2) 72.15,23.2 72.29,23.34 72.66,23.34 73.21,22.8 R206.1
  BOTTOM w0.3: v1(56.75,21.15) 56.9,21.3 69.8,21.3 v1(71.7,23.2)
SCL: length 9.6
  TOP w0.5: CN202.3 33.12,6.87 v1(32.8,6.55)
  BOTTOM w0.3: R222.2 v1(32.8,6.55) 34.85,4.5 R227.2
SDA: length 7.5
  TOP w0.5: v1(34.6,6.55) 35.12,7.07 CN202.4
  BOTTOM w0.3: R228.2 35.45,5.7 v1(34.6,6.55) R221.2
SHLD_SNS: length 38.3
  TOP w0.2: IC202.7 46.5,15 46.2,14.7 45.15,14.7 v1(44.45,14)
  CONDUCTIVE3 w0.3: 72.55,4.9 69.85,7.6 48.7,7.6 47.8,8.5 47.8,13.05 46.15,14.7 44.7,14.7 44.45,14.45 v1(44.45,14)
  vias: v1(72.55,5.65) v1(72.55,2.25) v1(73,1.4) v1(73.4,5.65) v1(73.4,2.25) v1(74.25,5.65) v1(74.25,2.25) v1(74.5,1.4) v1(75.1,5.65) v1(75.1,2.25) v1(75.25,7.25) v1(76,1.5) v1(76.25,7.25) v1(77.25,7.25) v1(77.25,1.5) v1(78.25,8) v1(78.5,1.5) v1(79,8.75) v1(79.5,2.25) v1(80.5,3.25) v1(81.5,4.25) v1(83.45,13.25) v1(83.45,12.35) v1(83.45,11.45) v1(83.45,10.55) v1(84.35,13.25) v1(84.35,12.35) v1(84.35,11.45) v1(84.35,10.55) v1(85.25,13.25) v1(85.25,12.35) v1(85.25,11.45) v1(85.25,10.55) v1(86.15,13.25) v1(86.15,12.35) v1(86.15,11.45) v1(86.15,10.55)
SIG310: length 4.1
  BOTTOM w0.3: 56.78,15.04 55.73,15.04 55.72,15.03 55.72,15.94 55.06,16.6 v1(53.9,16.6)
SIG311: length 0.8
  BOTTOM w0.3: R233.1 C252.2
SIG313: length 1.9
  BOTTOM w0.3: R238.2 59.25,16.17 R236.1 60.17,16.97 C254.2
SIG316: length 1.9
  BOTTOM w0.3: 60.31,15.18 60.17,15.04 R241.2 60.16,14.25 R240.1
SIG318: length 8.7
  BOTTOM w0.3: R236.2 58.4,14.27 R240.2 ; v1(53.85,18.55) 54.2,18.2 56.6,18.2 56.82,17.98 C253.2 58.42,16.85
SIG319: length 1.9
  TOP w0.2: 53.1,20.18 52.88,20.18 51.7,19 51.7,18.95
SIG324: length 2.5
  TOP w0.2: 52.2,18.95 52.4,18.95 52.73,19.27 54.58,19.27
SIG328: length 3.1
  TOP w0.2: 51.2,18.8 51.2,19.1 53.11,21.01 53.17,20.95
SIG335: length 8.5
  BOTTOM w0.3: v1(44.5,15.75) 43.6,15.75 40.88,18.48 C244.1 40.85,21.18 R224.1
SIG337: length 7.4
  BOTTOM w0.3: R223.1 41.84,22.23 41.84,22.18 41.73,22.07 C244.2 41.73,18.38 43.4,16.7 v1(44.5,16.7)
SIG369: length 10.4
  BOTTOM w0.3: R227.1 39.7,4.5 TP223.1 40.25,4.95 41.05,4.95 45.5,9.4 45.7,9.4 v1(46.65,10.35)
SIG370: length 10.9
  BOTTOM w0.3: R228.1 TP224.1 40.85,5.7 46.4,11.25 v1(47.25,11.25)
SIG422: length 1.3
  BOTTOM w0.5: D203.A 44.88,27.7
SIG438: length 11.6
  CONDUCTIVE3 w0.4: v1(28.1,27.9) 28.1,24.25 v1(33.05,19.3)
  BOTTOM w0.4: R217.2 32.12,19.3 v1(33.05,19.3) 33.08,19.3

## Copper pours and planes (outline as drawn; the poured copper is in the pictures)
GND_A on TOP: outline of 90 points within 47.55,8.34 57.19,17
GND_A on TOP: 26,1 25.89,1.04 25.85,1.15 25.85,4.65 25.89,4.76 26,4.8 35.45,4.8 36.55,5.9 36.55,10.85 36.59,10.96 36.7,11 38.84,11 38.94,10.96 40.51,9.39 40.55,9.29 40.55,1.15 40.51,1.04 40.4,1
GND_A on TOP: 88.05,17.1 88.01,17.11 88,17.15 88,23.8 88.01,23.84 88.05,23.85 88.95,23.85 88.99,23.84 89,23.8 89,17.15 88.99,17.11 88.95,17.1
GND_A on BOTTOM: 87.72,16.4 87.7,16.4 87.69,16.41 87.26,16.84 87.25,16.85 87.25,16.87 87.25,19.9 86.4,20.75 85.58,20.75 85.54,20.76 85.53,20.8 85.53,21.25 85.54,21.29 85.58,21.3 85.7,21.3 86,21.6 86,22.3 85.7,22.6 85.58,22.6 85.54,22.61 85.53,22.65 85.53,23.1 85.54,23.14 85.58,23.15 86.98,23.15 87.23,23.4 87.23,23.73 87.23,23.75 87.24,23.76 87.74,24.26 87.75,24.27 87.77,24.27 88.75,24.27 88.86,24.23 88.9,24.12 88.9,16.55 88.86,16.44 88.75,16.4
GND_A on BOTTOM: 36.85,6.75 36.81,6.76 36.8,6.8 36.8,7.65 36.81,7.69 36.85,7.7 40.7,7.7 44.24,11.24 44.25,11.25 44.27,11.25 44.9,11.25 45.89,12.24 45.9,12.25 45.92,12.25 48.08,12.25 48.1,12.25 48.11,12.24 48.84,11.51 48.85,11.5 48.85,11.48 48.85,9.25 49.1,9 49.85,9 50.24,9.39 50.25,9.4 50.27,9.4 50.75,9.4 50.79,9.39 50.8,9.35 50.8,9.02 50.8,9 50.79,8.99 50.41,8.61 50.4,8.6 50.38,8.6 49.85,8.6 49.61,8.36 49.6,8.35 49.58,8.35 47.95,8.35 47.91,8.36 47.9,8.4 47.9,11.55 47.6,11.85 46.3,11.85 41.21,6.76 41.2,6.75 41.18,6.75
GND_A on BOTTOM: 52.3,8.25 52.19,8.29 52.15,8.4 52.15,9.43 52.15,9.45 52.16,9.46 53.04,10.34 53.05,10.35 53.07,10.35 55.15,10.35 55.4,10.6 55.4,14.05 55.44,14.16 55.55,14.2 55.9,14.2 56.01,14.16 56.05,14.05 56.05,12.1 56.25,11.9 57.19,11.9 57.39,12.1 57.39,15.43 57.07,15.74 57.04,15.79 57.02,15.85 57.02,16.15 57.07,16.26 57.17,16.3 57.45,16.3 57.51,16.29 57.56,16.26 57.93,15.88 57.95,15.84 57.95,14.66 57.91,14.54 57.9,14.45 57.9,14.05 57.98,13.82 58.18,13.69 58.2,13.68 58.33,13.55 61.3,13.55 61.55,13.8 61.55,19.17 61.59,19.27 61.7,19.32 62.5,19.32 62.61,19.27 62.65,19.17 62.65,13.56 62.64,13.5 62.61,13.46 61.8,12.65 61.78,12.63 61.76,12.63 59.03,12.63 57.41,11.01 57.39,11 57.37,10.99 57.37,10.98 57.36,10.96 54.71,8.31 54.7,8.3 54.68,8.3 53.2,8.3 53.16,8.26 53.15,8.25 53.13,8.25
GND_A on CONDUCTIVE2: 48.35,10.38 48.35,10.4 48.36,10.41 48.84,10.89 48.85,10.9 48.87,10.9 52.55,10.9 59.24,17.59 59.25,17.6 59.27,17.6 75.23,17.6 82.46,24.83 82.53,24.86 87.9,24.86 87.93,24.85 87.97,24.83 88.92,23.88 88.94,23.85 88.95,23.81 88.95,17.29 88.94,17.25 88.92,17.22 86.53,14.83 86.51,14.82 86.49,14.81 82.78,14.81 78.31,10.34 78.3,10.33 78.28,10.33 56.88,10.33 54.99,8.44 54.97,8.43 54.95,8.42 48.62,8.42 48.6,8.43 48.59,8.44 48.36,8.66 48.35,8.68 48.35,8.69 ; 7 cut-outs
GND_A on CONDUCTIVE3: 48.35,12.43 48.35,12.45 48.36,12.46 48.72,12.82 48.74,12.83 48.76,12.84 52.03,12.84 52.93,13.73 52.93,15.23 52.94,15.25 52.95,15.26 53.81,16.13 53.83,16.14 53.85,16.14 54.11,16.21 54.31,16.39 54.32,16.39 54.44,16.51 54.45,16.52 54.47,16.52 55.5,16.52 56.61,17.64 56.63,17.65 56.65,17.65 75.28,17.65 82.46,24.83 82.5,24.85 82.53,24.86 87.75,24.86 87.78,24.85 87.82,24.83 88.87,23.78 88.89,23.75 88.9,23.71 88.9,17.29 88.89,17.25 88.87,17.22 86.48,14.83 86.46,14.82 86.44,14.81 82.78,14.81 78.31,10.34 78.3,10.33 78.28,10.33 57.13,10.33 55.03,8.23 55,8.21 54.96,8.2 48.72,8.2 48.7,8.2 48.69,8.21 48.36,8.54 48.35,8.55 48.35,8.57 ; 4 cut-outs
GND_P on TOP: 58.55,24.2 58.44,24.24 58.4,24.35 58.4,25.74 58.41,25.8 58.44,25.84 58.75,26.15 58.75,27.35 58.76,27.39 58.8,27.4 59.2,27.4 59.88,28.07 59.88,38.95 59.89,38.99 59.92,39 78.9,39 79.01,38.96 79.05,38.85 79.05,32.47 79.05,32.45 79.04,32.44 78.55,31.95 78.55,31.61 78.54,31.58 78.5,31.56 73.92,31.56 73.86,31.59 70.85,34.6 69,34.6 68.25,33.85 68.25,28.5 68.65,28.1 69.24,28.1 69.35,28.06 69.39,27.95 69.39,26.56 70.66,25.29 70.69,25.25 70.7,25.19 70.7,24.35 70.66,24.24 70.55,24.2
GND_P on TOP: outline of 267 points within 1.05,1 75.65,38.93
GND_P on BOTTOM: outline of 89 points within 0.95,1 82.5,38.95 ; 1 cut-out
GND_P on BOTTOM: 32.61,13.89 32.6,13.9 32.6,13.92 32.6,14.95 32.4,15.15 29.05,15.15 29.01,15.16 29,15.2 29,15.9 29.01,15.94 29.05,15.95 29.75,15.95 30.56,16.76 30.58,16.77 30.6,16.77 33.27,16.77 34.69,18.19 34.7,18.2 34.72,18.2 38.13,18.2 38.15,18.2 38.16,18.19 38.44,17.91 38.45,17.9 38.45,17.88 38.45,11.52 38.45,11.5 38.44,11.49 38.16,11.21 38.15,11.2 38.13,11.2 33.45,11.2 33.41,11.21 33.4,11.25 33.4,12.55 32.76,13.19 32.75,13.2 32.75,13.22 32.75,13.75 ; 1 cut-out
GND_P on BOTTOM: 48.09,13.7 47.99,13.74 47.94,13.85 47.94,14.11 44.7,17.35 43.59,17.35 43.57,17.35 43.56,17.36 42.41,18.51 42.4,18.52 42.4,18.54 42.4,21.45 42.41,21.49 42.45,21.5 42.65,21.7 42.65,21.95 42.66,21.99 42.7,22 43.15,22 43.19,21.99 43.2,21.95 43.2,21.46 44.19,20.47 44.2,20.46 44.2,20.44 44.2,18.95 45.35,17.8 51.85,17.8 51.96,17.76 52,17.65 52,13.85 51.96,13.74 51.85,13.7
GND_P on CONDUCTIVE2: outline of 182 points within 0.99,1 81.75,38.98 ; 13 cut-outs
GND_P on CONDUCTIVE3: 60.17,8.2 60.15,8.2 60.14,8.21 59.91,8.44 59.9,8.45 59.9,8.47 59.9,9.13 59.9,9.15 59.91,9.16 60.19,9.44 60.2,9.45 60.22,9.45 73.38,9.45 73.4,9.45 73.41,9.44 73.69,9.16 73.7,9.15 73.7,9.13 73.7,8.92 73.7,8.9 73.69,8.89 73.01,8.21 73,8.2 72.98,8.2
GND_P on CONDUCTIVE3: outline of 122 points within 0.95,1.05 81.9,38.86 ; 20 cut-outs
VBAT on BOTTOM: 39.3,18.62 39.42,18.9 39.7,19.02 39.98,18.9 40.1,18.62 40.1,17.15 39.7,16.75 39.3,17.15
VBAT on CONDUCTIVE2: 44.86,11.86 44.71,11.89 44.58,11.97 44.17,12.38 44.08,12.51 44.05,12.66 44.05,12.95 44.45,13.35 44.85,12.95 44.85,12.83 45.02,12.66 51.44,12.66 53,14.22 53,14.8 53.02,14.91 53.09,15.01 55.25,17.17 55.25,17.22 55.34,17.43 55.55,17.52 55.58,17.52 55.79,17.43 55.88,17.22 55.88,17.08 55.86,16.96 55.79,16.87 53.95,15.03 53.95,15 53.95,14.2 53.92,14.05 53.83,13.92 51.89,11.97 51.76,11.89 51.61,11.86
VBUS on TOP: 77.05,24.22 76.99,24.23 76.95,24.26 76.39,24.82 76.36,24.87 76.35,24.92 76.35,30.85 76.39,30.96 76.5,31 78.34,31 78.44,30.96 78.76,30.64 78.8,30.54 78.8,29.95 79.15,29.6 82.15,29.6 82.26,29.56 82.3,29.45 82.3,24.55 82.26,24.44 82.15,24.4 79.01,24.4 78.87,24.26 78.82,24.23 78.77,24.22
VDD on TOP: 49.79,9.43 49.67,9.38 49.61,9.5 49.7,9.7 49.6,9.8 49.4,9.71 49.28,9.77 49.33,9.89 49.55,9.99 50.53,10.97 50.53,11.42 50.13,11.82 50.1,11.89 50.1,13.05 50.2,13.15 50.3,13.05 50.3,12.1 50.97,11.43 50.99,11.4 51,11.36 51,10 50.97,9.93 50.9,9.9 50.05,9.9 49.97,9.82
VDD on BOTTOM: 29.2,6.28 29.14,6.34 29.14,6.35 28.9,6.35 28.79,6.39 28.75,6.5 28.75,7.65 28.76,7.71 28.79,7.76 29.84,8.81 29.89,8.84 29.95,8.85 40.4,8.85 43.64,12.09 43.65,12.1 43.67,12.1 44.7,12.1 45.15,12.55 45.15,12.9 45.16,12.94 45.2,12.95 45.8,12.95 45.84,12.94 45.85,12.9 45.85,12.62 45.85,12.6 45.84,12.59 44.91,11.66 44.9,11.65 44.88,11.65 43.9,11.65 40.49,8.24 40.45,8.21 40.39,8.2 35.8,8.2 35.76,8.19 30.39,8.19 29.48,7.28 29.47,6.46 29.46,6.43 29.41,6.33 29.35,6.28 29.28,6.25
VIN on TOP: 17.14,4.46 17.08,4.47 17.03,4.51 16.03,5.51 14.86,5.51 14.76,5.55 14.71,5.66 14.71,6.14 14.63,6.22 14.27,6.22 14.15,6.1 14.15,5.66 14.11,5.55 14,5.51 13.46,5.51 13.35,5.55 13.31,5.66 13.31,6.08 13.18,6.21 12.88,6.21 12.75,6.08 12.75,5.91 12.71,5.81 12.6,5.76 12.31,5.76 12.2,5.81 12.16,5.91 12.16,6.2 12.15,6.23 12.14,6.26 12.14,15.93 12.16,15.98 12.19,16.03 14.76,18.61 14.87,18.65 16.85,18.65 16.96,18.61 18.26,17.3 18.3,17.2 18.3,15.71 18.29,15.65 18.26,15.61 17.15,14.5 17.15,8.55 17.85,7.85 18.15,7.85 18.26,7.81 18.3,7.7 18.3,4.61 18.26,4.51 18.15,4.46
VIN2 on TOP: 20.4,4.51 20.37,4.51 20.33,4.53 19.82,4.53 19.71,4.57 19.67,4.68 19.67,7.7 19.71,7.81 19.82,7.85 20.2,7.85 20.57,8.22 20.57,12.98 20.58,13 20.59,13.01 21.01,13.44 21.03,13.45 21.05,13.45 22.27,13.45 22.29,13.45 22.31,13.44 24.86,10.89 24.9,10.79 24.9,8.51 24.89,8.45 24.86,8.41 23.55,7.1 23.55,5.52 23.5,5.41 23.4,5.37 21.81,5.37 21,4.55 20.95,4.52 20.89,4.51
VIN2 on BOTTOM: 21.67,6.7 21.65,6.7 21.64,6.71 20.74,7.61 20.73,7.63 20.73,7.64 20.73,23.58 20.73,23.6 20.74,23.61 23.19,26.06 23.2,26.07 23.22,26.07 26.25,26.07 26.29,26.06 26.3,26.02 26.3,19.7 27.4,18.6 30.23,18.6 30.25,18.6 30.26,18.59 30.99,17.86 31,17.85 31,17.83 31,17.15 30.99,17.11 30.95,17.1 30.72,17.1 30.7,17.1 30.69,17.11 30.64,17.16 30.63,17.18 30.62,17.2 30.62,17.55 30.32,17.85 27.55,17.85 26.8,17.1 26.8,7.17 26.8,7.15 26.79,7.14 26.36,6.71 26.35,6.7 26.33,6.7
VIN2 on CONDUCTIVE2, CONDUCTIVE3: 21.5,6.65 21.46,6.66 21.45,6.7 21.45,12.85 21.46,12.89 21.5,12.9 23.13,12.9 23.15,12.9 23.16,12.89 24.94,11.11 24.95,11.1 24.95,11.08 24.95,8.32 24.95,8.3 24.94,8.29 23.31,6.66 23.3,6.65 23.28,6.65
ADDR on TOP: 50.6,19.2 50.61,19.24 50.63,19.27 51.75,20.4 51.75,20.91 51.78,20.98 51.85,21.01 52.33,21.01 52.4,20.98 52.43,20.91 52.43,20.87 52.42,20.83 52.4,20.8 52.2,20.6 52.19,20.56 52.17,20.53 50.8,19.16 50.8,18.95 50.7,18.85 50.6,18.95
ADDR on BOTTOM: 59.2,18.8 59.09,18.84 59.05,18.95 59.05,19.47 58.83,19.69 58.1,19.69 57.91,19.49 57.86,19.46 57.8,19.45 57.09,19.45 57.03,19.46 56.98,19.49 56.79,19.69 55.37,19.69 55.32,19.7 55.27,19.73 54.15,20.85 52.82,20.85 52.2,20.66 52.16,20.66 52.02,20.74 52.03,20.89 52.06,20.92 52.08,20.94 52.11,20.95 52.27,21 52.11,21.05 52.08,21.06 52.06,21.08 52.03,21.11 52.02,21.26 52.16,21.34 52.2,21.34 52.82,21.15 54.21,21.15 54.27,21.14 54.32,21.11 55.43,19.99 56.85,19.99 56.91,19.98 56.96,19.94 57.15,19.75 57.74,19.75 57.93,19.94 57.98,19.98 58.04,19.99 58.9,19.99 58.95,19.98 59.31,19.63 59.32,19.59 59.62,19.3 60.3,19.3 60.41,19.26 60.45,19.15 60.45,18.95 60.41,18.84 60.3,18.8
ALERT on TOP: 54.43,11 54.39,11.01 54.35,11.03 53.83,11.55 53.35,11.55 53.31,11.56 53.28,11.58 52.35,12.5 52.2,12.5 52.13,12.53 52.1,12.6 52.1,12.74 52.13,12.81 52.2,12.84 52.26,12.84 52.3,12.83 52.33,12.81 53.39,11.75 53.88,11.75 53.91,11.74 53.95,11.72 54.21,11.46 54.7,11.46 54.77,11.43 54.8,11.36 54.8,11.1 54.77,11.03 54.7,11
BIAS on BOTTOM: 57.44,18.4 57.4,18.41 57.37,18.43 57.2,18.6 55,18.6 54.9,18.62 54.82,18.67 54.2,19.3 53.54,19.3 52.92,18.67 52.88,18.65 52.85,18.64 49.52,18.64 49.45,18.67 49.42,18.74 49.42,18.95 49.45,19.02 49.52,19.05 52.45,19.05 52.65,19.25 52.65,19.7 52.72,19.88 52.9,19.95 54.15,19.95 54.25,19.93 54.33,19.88 54.9,19.3 56.21,19.3 56.25,19.29 56.28,19.27 56.4,19.15 58,19.15 58.17,19.32 58.2,19.34 58.24,19.35 58.5,19.35 58.57,19.32 58.6,19.25 58.6,18.86 58.57,18.79 58.5,18.76 58.21,18.76 57.88,18.43 57.85,18.41 57.81,18.4
BST1 on TOP: 46.77,17.9 46.75,17.9 46.73,17.92 46.72,17.93 46.7,17.95 46.7,17.97 46.7,18.85 46.25,19.3 46.07,19.3 46.05,19.3 46.04,19.31 45.96,19.39 45.95,19.4 45.95,19.42 45.95,19.98 45.95,20 45.96,20.01 46.79,20.84 46.8,20.85 46.82,20.85 47.1,20.85 47.14,20.84 47.15,20.8 47.15,20.64 47.14,20.61 47.11,20.59 47.01,20.56 46.92,20.5 46.75,20.33 46.68,20.23 46.62,20.07 46.62,19.77 46.79,19.55 46.88,19.45 46.9,19.44 46.9,19.41 46.9,18.1 47.15,18.1 47.19,18.09 47.2,18.05 47.2,17.95 47.19,17.91 47.15,17.9
CSN1 on TOP: 41.82,24.65 41.8,24.65 41.79,24.66 41.51,24.94 41.5,24.95 41.5,24.97 41.5,25.05 41.51,25.09 41.55,25.1 42.15,25.1 42.19,25.09 42.2,25.05 42.2,24.7 42.19,24.66 42.15,24.65
CSN1 on TOP: 38.2,24.6 38.09,24.64 38.05,24.75 38.05,28.9 38.09,29.01 38.2,29.05 40.85,29.05 40.96,29.01 41,28.9 41,26.16 40.96,26.06 40.3,25.4 40.3,24.75 40.26,24.64 40.15,24.6
CSN1 on BOTTOM, CONDUCTIVE3: 39.05,26.5 38.94,26.54 38.9,26.65 38.9,28.9 38.94,29.01 39.05,29.05 40.9,29.05 41.01,29.01 41.05,28.9 41.05,26.65 41.01,26.54 40.9,26.5
CSN1 on CONDUCTIVE2: 39.05,26.5 38.94,26.54 38.9,26.65 38.9,28.95 38.94,29.06 39.05,29.1 40.9,29.1 41.01,29.06 41.05,28.95 41.05,26.65 41.01,26.54 40.9,26.5
CSN2 on TOP: 72.95,23.8 72.91,23.81 72.9,23.85 72.9,24.05 70.19,26.76 70.16,26.8 70.15,26.86 70.15,28.3 69.14,29.31 69.11,29.35 69.1,29.41 69.1,32.55 69.14,32.66 69.25,32.7 70.79,32.7 70.85,32.69 70.89,32.66 72.55,31 75.25,31 75.29,30.99 75.3,30.95 75.3,30.27 75.3,30.25 75.29,30.24 75.1,30.05 75.1,23.85 75.09,23.81 75.05,23.8
CSP1 on TOP: 40.7,24 40.66,24.01 40.65,24.05 40.65,24.18 40.65,24.2 40.66,24.21 41.09,24.64 41.1,24.65 41.12,24.65 41.25,24.65 41.29,24.64 41.3,24.6 41.3,24.05 41.29,24.01 41.25,24
CSP1 on TOP: 29.69,22.31 29.66,22.36 29.65,22.41 29.65,34.16 29.65,34.18 29.66,34.19 30.56,35.09 30.57,35.1 30.59,35.1 37.49,35.1 37.53,35.09 37.54,35.05 37.54,24.33 37.97,23.9 40.14,23.9 40.24,23.86 40.35,23.75 41.15,23.75 41.19,23.74 41.2,23.7 41.2,20.87 41.2,20.85 41.19,20.84 40.76,20.42 40.75,20.41 40.73,20.4 31.66,20.4 31.6,20.41 31.55,20.45
CSP1 on CONDUCTIVE2, CONDUCTIVE3: 34.27,24.15 34.25,24.15 34.24,24.16 33.16,25.24 33.15,25.25 33.15,25.27 33.15,30.35 33.16,30.39 33.2,30.4 37.4,30.4 37.44,30.39 37.45,30.35 37.45,26.17 37.45,26.15 37.44,26.14 35.46,24.16 35.45,24.15 35.43,24.15
CSP2 on TOP: 51.7,21.75 51.59,21.79 51.55,21.9 51.55,24.2 51.59,24.31 51.7,24.35 55.84,24.35 55.94,24.31 56.06,24.19 56.11,24.08 56.11,22.25 56.06,22.14 55.96,22.1 55.6,22.1 55.29,21.79 55.25,21.76 55.19,21.75
CSP2 on BOTTOM: 52.6,21.85 52.49,21.89 52.45,22 52.45,23.43 52.45,23.45 52.46,23.46 53.04,24.04 53.05,24.05 53.07,24.05 55.35,24.05 55.46,24.01 55.5,23.9 55.5,22 55.46,21.89 55.35,21.85
CSP2 on CONDUCTIVE2: 51.9,21.85 51.79,21.89 51.75,22 51.75,23.9 51.79,24.01 51.9,24.05 54.15,24.05 54.26,24.01 54.3,23.9 54.3,22 54.26,21.89 54.15,21.85
CSP2 on CONDUCTIVE3: 51.75,21.91 51.64,21.96 51.6,22.06 51.6,23.75 51.64,23.86 51.75,23.9 53.99,23.9 54.09,23.86 54.13,23.75 54.13,22.06 54.09,21.96 53.99,21.91
DH1_Q on BOTTOM: 42.75,25.4 42.66,25.42 42.58,25.47 42.1,25.95 41.92,26.02 41.85,26.2 41.85,26.25 41.92,26.43 42.1,26.5 42.3,26.5 42.39,26.48 42.47,26.43 42.85,26.05 43.45,26.05 43.67,26.27 43.67,27.7 43.92,27.95 44.17,27.7 44.17,26.9 44.62,26.45 45.46,26.45 45.71,26.2 45.46,25.95 45.4,25.95 45.31,25.84 45.17,25.8 44.55,25.8 44.22,25.47 44.14,25.42 44.05,25.4
DH2 on BOTTOM: 49.35,20.5 49.17,20.57 49.1,20.75 49.1,21.6 49.12,21.69 49.17,21.77 49.75,22.35 49.75,23.21 49.71,23.24 48.9,24.05 48.8,24.05 48.62,24.12 48.55,24.3 48.55,24.5 48.7,24.73 48.98,24.67 49.05,24.6 49.08,24.57 49.75,23.9 50.23,23.9 50.4,23.83 50.48,23.65 50.48,22.13 50.47,22.07 50.4,21.95 49.7,21.25 49.7,20.88 49.71,20.63 49.49,20.5
DH2_Q on BOTTOM: 50.19,24.45 49.9,24.45 49.72,24.52 49.65,24.7 49.65,25.45 49.67,25.54 49.72,25.62 50.1,26 50.1,26.78 50.12,26.87 50.16,26.94 50.16,27.3 50.18,27.39 50.23,27.47 50.49,27.73 50.57,27.78 50.66,27.8 54,27.8 54.09,27.78 54.17,27.73 54.4,27.5 55.3,27.5 55.48,27.43 55.55,27.25 55.55,27.24 55.49,27.09 55.35,27 54.97,26.62 54.89,26.57 54.8,26.55 54.45,26.55 54.36,26.57 54.28,26.62 53.65,27.25 51.2,27.25 50.67,26.72 50.67,25.76 50.65,25.67 50.6,25.58 50.51,25.5 50.51,25.38 50.5,25.31 50.48,25.25 50.48,24.7 50.4,24.52 50.23,24.45
DL1_Q on BOTTOM: 44.52,20.9 44.5,20.9 44.49,20.91 43.91,21.49 43.9,21.5 43.9,21.52 43.9,22.25 43.45,22.7 42.75,22.7 42.71,22.71 42.7,22.75 42.7,24.3 42.71,24.34 42.75,24.35 43.35,24.35 43.39,24.34 43.4,24.3 43.4,23.65 44.44,22.61 44.45,22.6 44.45,22.58 44.45,21.65 44.55,21.55 45.08,21.55 45.1,21.55 45.11,21.54 45.29,21.36 45.3,21.35 45.3,21.33 45.3,20.95 45.29,20.91 45.25,20.9
DL2 on BOTTOM: 50.9,21 50.86,21.01 50.85,21.05 50.85,21.68 50.85,21.7 50.86,21.71 51.4,22.25 51.4,24.15 51.41,24.19 51.45,24.2 51.8,24.2 52.84,25.24 52.85,25.25 52.87,25.25 53.25,25.25 53.29,25.24 53.3,25.2 53.3,24.5 53.29,24.46 53.25,24.45 52.9,24.45 52,23.55 52,22.07 52,22.05 51.99,22.04 51.55,21.6 51.55,21.05 51.54,21.01 51.5,21
DL2_Q on TOP: 55.65,25.7 55.61,25.71 55.6,25.75 55.6,27.1 55.61,27.14 55.65,27.15 56.35,27.15 56.39,27.14 56.4,27.1 56.4,25.87 56.4,25.85 56.39,25.84 56.26,25.71 56.25,25.7 56.23,25.7
DL2_Q on BOTTOM: 54.2,24.45 54.16,24.46 54.15,24.5 54.15,25.45 53.9,25.7 53.55,25.7 53.51,25.71 53.5,25.75 53.5,26.2 53.51,26.24 53.55,26.25 54.03,26.25 54.05,26.25 54.06,26.24 54.4,25.9 55.4,25.9 55.64,26.14 55.65,26.15 55.67,26.15 57.05,26.15 57.09,26.14 57.1,26.1 57.1,25.45 57.09,25.41 57.05,25.4 56.1,25.4 55.16,24.46 55.15,24.45 55.13,24.45
HVDP on TOP: 54.45,11.95 54.38,11.98 54.35,12.05 54.35,12.96 53.41,13.9 52.9,13.9 52.8,14 52.9,14.1 53.45,14.1 53.49,14.09 53.52,14.07 54.83,12.76 54.85,12.73 54.86,12.69 54.86,12.45 54.97,12.08 54.95,11.99 54.87,11.95
LX1 on TOP: 44.95,21.9 44.91,21.91 44.9,21.95 44.9,25.65 44.6,25.95 43.77,25.95 43.75,25.95 43.74,25.96 42.26,27.44 42.25,27.45 42.25,27.47 42.25,27.85 41.85,28.25 41.4,28.25 41.36,28.26 41.35,28.3 41.35,29.03 41.35,29.05 41.36,29.06 44.05,31.75 44.05,36.4 44.06,36.44 44.1,36.45 47.25,36.45 47.29,36.44 47.3,36.4 47.3,24.07 47.3,24.05 47.29,24.04 46.5,23.25 46.5,21.95 46.49,21.91 46.45,21.9
LX1 on TOP: 48.15,18.4 48.11,18.41 48.1,18.45 48.1,20.2 47.66,20.64 47.65,20.65 47.65,20.67 47.65,21.13 47.65,21.15 47.66,21.16 47.9,21.4 47.9,22.15 47.55,22.5 47.3,22.5 47.26,22.51 47.25,22.55 47.25,23.15 47.26,23.19 47.3,23.2 47.83,23.2 47.85,23.2 47.86,23.19 48.29,22.76 48.3,22.75 48.3,22.73 48.3,18.45 48.29,18.41 48.25,18.4
LX1 on BOTTOM: 44.6,23.05 44.49,23.09 44.45,23.2 44.45,24.96 44.49,25.06 44.6,25.11 46.4,25.11 46.51,25.06 46.55,24.96 46.55,23.2 46.51,23.09 46.4,23.05
LX1 on CONDUCTIVE2, CONDUCTIVE3: 43.8,23.05 43.69,23.09 43.65,23.2 43.65,24.96 43.69,25.06 43.8,25.11 46.4,25.11 46.51,25.06 46.55,24.96 46.55,23.2 46.51,23.09 46.4,23.05
LX2 on TOP: 51.65,24.7 51.54,24.74 51.5,24.85 51.5,25.9 50.61,26.79 50.6,26.8 50.6,26.82 50.6,36.2 50.64,36.31 50.75,36.35 53.23,36.35 53.26,36.34 53.27,36.3 53.27,33.08 56.4,29.95 58.53,29.95 58.55,29.95 58.56,29.94 58.95,29.55 58.99,29.54 59,29.5 59,27.8 58.99,27.76 58.95,27.75 54.55,27.75 52.35,25.55 52.35,24.75 52.34,24.71 52.3,24.7
LX2 on BOTTOM, CONDUCTIVE2, CONDUCTIVE3: 56.4,26.95 56.29,26.99 56.25,27.1 56.25,29.42 56.29,29.53 56.4,29.57 58.1,29.57 58.21,29.53 58.25,29.42 58.25,27.1 58.21,26.99 58.1,26.95
OUT on TOP: 58.02,12.75 57.99,12.76 57.98,12.8 57.98,17.78 57.98,17.8 57.99,17.81 58.28,18.11 58.28,18.6 58.28,18.61 58.29,18.89 58.17,19.14 58.16,19.17 58.16,20.67 56.71,22.12 56.7,22.13 56.69,22.15 56.69,25.37 56.7,25.39 56.71,25.41 57.11,25.81 57.21,25.85 57.75,25.85 57.86,25.81 57.9,25.7 57.9,24.3 58.07,24.13 58.11,24.08 58.15,24.05 58.6,23.6 59.94,23.6 60,23.59 60.04,23.56 60.4,23.2 61.83,23.2 61.85,23.2 61.86,23.19 62.42,22.62 71.1,22.62 71.12,22.62 71.14,22.61 71.3,22.45 72.7,22.45 72.9,22.65 72.9,23.1 72.91,23.14 72.95,23.15 75.03,23.15 75.05,23.15 75.06,23.14 76.09,22.11 76.1,22.1 76.1,22.08 76.1,14.75 76.06,14.64 75.95,14.6 61.35,14.6 59.85,13.1 59.85,12.8 59.84,12.76 59.8,12.75
SHLD_SNS on TOP: 72.88,0.99 72.86,0.99 72.84,1 72.16,1.69 72.15,1.7 72.14,1.72 72.14,5.72 72.15,5.74 72.16,5.76 72.44,6.04 72.45,6.05 72.47,6.05 74.2,6.05 74.2,6.45 73.51,6.45 73.41,6.49 73.36,6.6 73.36,7.61 73.41,7.72 73.51,7.76 77.51,7.76 79.15,9.4 79.15,11.55 79.16,11.59 79.2,11.6 81.1,11.6 81.1,12.4 79.2,12.4 79.16,12.41 79.15,12.45 79.15,13.55 79.16,13.59 79.2,13.6 81.15,13.6 81.15,14.4 79.2,14.4 79.16,14.41 79.15,14.45 79.15,15.6 79.16,15.64 79.2,15.65 84.35,15.65 85.29,16.59 85.29,28.04 82.9,30.43 80.88,30.43 80.77,30.47 80.73,30.58 80.73,32.57 80.77,32.68 80.88,32.72 88.78,32.72 88.88,32.68 88.93,32.57 88.93,27.29 88.92,27.24 88.9,27.19 88.9,25.78 88.88,25.73 88.85,25.68 86.89,23.72 86.89,17.26 88.91,15.24 88.92,15.22 88.93,15.2 88.93,7.65 88.88,7.54 88.78,7.5 85.45,7.5 78.95,1 78.94,0.99 78.92,0.99
SHLD_SNS on BOTTOM: 72.21,1.59 72.2,1.6 72.2,1.62 72.2,5.83 72.2,5.85 72.21,5.86 74.04,7.69 74.05,7.7 74.07,7.7 77.4,7.7 83.57,13.87 83.59,13.88 83.61,13.89 86.63,13.89 86.67,13.87 86.68,13.84 86.68,8.75 86.68,8.73 86.67,8.72 78.95,1 78.94,0.99 78.92,0.99 72.88,0.99 72.77,1.03
SHLD_SNS on CONDUCTIVE3: 72.21,1.64 72.2,1.65 72.2,1.67 72.2,5.83 72.2,5.85 72.21,5.86 74.19,7.84 74.2,7.85 74.22,7.85 77.55,7.85 83.64,13.94 83.66,13.95 83.67,13.95 86.64,13.95 86.68,13.94 86.69,13.9 86.69,8.76 86.69,8.74 86.68,8.73 78.95,1 78.94,0.99 78.92,0.99 72.93,0.99 72.82,1.03
SIG247 on BOTTOM: 29,11 28.96,11.01 28.95,11.05 28.95,13.2 28.96,13.24 29,13.25 29.78,13.25 29.8,13.25 29.81,13.24 30.9,12.15 31.25,12.15 31.9,12.8 31.9,14.6 31.91,14.64 31.95,14.65 32.3,14.65 32.34,14.64 32.35,14.6 32.35,12.55 32.74,12.16 32.75,12.15 32.75,12.13 32.75,11.2 32.74,11.16 32.7,11.15 30.9,11.15 30.76,11.01 30.75,11 30.73,11
